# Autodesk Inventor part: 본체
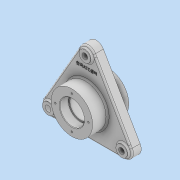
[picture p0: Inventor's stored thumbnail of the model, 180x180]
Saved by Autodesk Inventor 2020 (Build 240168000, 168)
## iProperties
Created: 2023-04
Part Number: 본체
Material: 일반
Document SubType Name: Modeling
Designer: oem
Density: 1 g/cm^3
Appearance: 기본값
Mass: 451.538 g
Surface Area: 640.896 cm^2
Volume: 451.538 cm^3
Author: oem
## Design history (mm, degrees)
sketch "스케치1" dims "d7" = 164
  geometry: L1 (0, 82)-(71.014, -41); L2 (71.014, -41)-(-71.014, -41); L3 (-71.014, -41)-(0, 82); L4 (-13.856, 90)-(-84.87, -33); L5 (84.87, -33)-(13.856, 90); L6 (-71.014, -57)-(71.014, -57); C1 r 40 at (0, 0); C2 r 57 at (0, 0); A1 r 16 centre (-71.014, -41) between (-84.87, -33) and (-71.014, -57); A2 r 16 centre (71.014, -41) between (71.014, -57) and (84.87, -33); A3 r 16 centre (0, 82) between (13.856, 90) and (-13.856, 90); 5 further points
  constraints: 12 end point, 11 coincident, 6 point on circle, 5 centre point, 5 tangent, 2 vertical alignment, 1 horizontal, 9 other
  dimensions: "d0" = 80 diameter of C1; "d3" = 32 diameter of A1; "d4" = 32 diameter of A2; "d5" = 32 diameter of A3; "d8" = 114 diameter of C2
extrude "돌출1" new body sketch "스케치1" stored distance "d9" = 18; taper "d10" = 0 deg
sketch "스케치2"
  geometry: C1 r 40 at (0, 0) reference; 1 further point
extrude "돌출2" join sketch "스케치2" distance "d11" = 23; taper "d12" = 0 deg
sketch "스케치3"
  geometry: C1 r 40 at (0, 0) reference; C2 r 45 at (0, 0)
  constraints: 1 centre point, 1 coincident
  dimensions: "d13" = 90 diameter of C2
extrude "돌출3" join sketch "스케치3" distance "d14" = 5; taper "d15" = 0 deg
sketch "스케치4"
  geometry: C1 r 40 at (0, 0) reference; 1 further point
extrude "돌출4" join sketch "스케치4" distance "d16" = 29; taper "d17" = 0 deg
node "작업 평면1"
sketch "스케치5"
  geometry: C1 r 11 at (-71.014, -41); C2 r 11 at (71.014, -41); C3 r 11 at (0, 82); A1 r 16 centre (-71.014, -41) between (-84.87, -33) and (-71.014, -57) reference; A2 r 16 centre (71.014, -41) between (71.014, -57) and (84.87, -33) reference; A3 r 16 centre (0, 82) between (13.856, 90) and (-13.856, 90) reference; 1 further point
  constraints: 3 centre point, 3 coincident
  dimensions: "d19" = 22 diameter of C1; "d20" = 22 diameter of C2; "d21" = 22 diameter of C3
extrude "돌출5" join sketch "스케치5" stored distance "d22" = 29; taper "d23" = 0 deg
sketch "스케치6"
  geometry: C1 r 11 at (0, 0) reference; C2 r 11 at (-71.014, -123) reference; C3 r 11 at (71.014, -123) reference; 4 further points
  constraints: 3 coincident
hole "구멍1" sketch "스케치6" at (0, 0), (-71.014, -123), (71.014, -123) diameter "d24" = 11; stored, may be unused: countersink angle "d28" = 90 deg, drill point angle "d30" = 120 deg; dims "d25" = 6, "d26" = 4, "d27" = 2, "d29" = 20
sketch "스케치7"
  geometry: C1 r 40 at (0, 0) reference; C2 r 21 at (0, 0)
  constraints: 1 centre point, 1 coincident
  dimensions: "d31" = 42 diameter of C2
extrude "돌출6" cut sketch "스케치7" extent not by distance; stored distance "d32" = 0; taper "d33" = 0 deg
sketch "스케치8"
  geometry: C1 r 21 at (0, 0) reference; C2 r 40 at (0, 0) reference; C3 r 23.5 at (0, 0)
  constraints: 1 centre point, 1 coincident
  dimensions: "d34" = 47 diameter of C3
extrude "돌출7" cut sketch "스케치8" distance "d35" = 17; taper "d36" = 0 deg
sketch "스케치9"
  geometry: C1 r 40 at (0, 0) reference; C2 r 23.5 at (0, 0)
  constraints: 1 centre point, 1 coincident
  dimensions: "d37" = 47 diameter of C2
extrude "돌출8" cut sketch "스케치9" distance "d38" = 17; taper "d39" = 0 deg
sketch "스케치10"
  geometry: C1 r 23.5 at (0, 0) reference; C2 r 40 at (0, 0) reference; A1 r 32 centre (0, 0) between (0, 32) and (-32, 0); 2 further points
  constraints: 4 point on circle, 2 horizontal alignment, 2 vertical alignment, 1 centre point, 1 coincident
  dimensions: "d40" = 64 diameter of A1
hole "구멍2" sketch "스케치10" at (0, 32), (-32, 0), (0, -32), (32, 0) diameter "d41" = 3.242; stored, may be unused: countersink angle "d45" = 90 deg, drill point angle "d47" = 120 deg; dims "d42" = 8, "d43" = 4, "d44" = 2, "d46" = 10
sketch "스케치11"
  geometry: C1 r 40 at (0, 0) reference; C2 r 32 at (0, 0); C3 r 1.621 at (0, 32) reference; C4 r 1.621 at (0, -32) reference; C5 r 1.621 at (32, 0) reference; C6 r 1.621 at (-32, 0) reference; 4 further points
  constraints: 5 coincident, 1 centre point
  dimensions: "d48" = 64 diameter of C2
hole "구멍3" sketch "스케치11" at (0, 32), (0, -32), (32, 0), (-32, 0) diameter "d49" = 3.242; stored, may be unused: countersink angle "d53" = 90 deg, drill point angle "d55" = 120 deg; dims "d50" = 8, "d51" = 4, "d52" = 2, "d54" = 10
sketch "스케치12"
  geometry: L1 (-71.014, -57)-(71.014, -57) reference; L2 (-22.5, 65)-(22.5, 65); L3 (22.5, 65)-(22.5, 55); L4 (22.5, 55)-(-22.5, 55); L5 (-22.5, 55)-(-22.5, 65); L6 (-22.5, 60)-(22.5, 60); C1 r 40 at (0, 0) reference; 1 further point
  constraints: 3 midpoint, 2 end point, 1 parallel, 1 vertical alignment, 2 other
  dimensions: "d58" = 60 distance from line of C1.centre L6; "d59" = 10 distance of L2.end L3.end; "d60" = 45 distance between parallel lines of L3 L5
fillet "모깎기1" dims "d61" = 0.6
fillet "모깎기2" dims "d62" = 3
extrude "돌출9" join sketch "스케치12" distance "d63" = 0.5; taper "d64" = 0 deg
chamfer "모따기1" distance "d65" = 1; stored, may be unused: second distance "d66" = 2, angle "d67" = 45 deg
node "솔리드1"
feature "A9D066F2-1C7D-4E18-AEED-F7BC21143FA4" dims "d24" = 11, "d25" = 6, "d26" = 4, "d27" = 2, "d28" = 90 deg, "d29" = 20, "d30" = 120 deg
other parameters: "d18" = 4
